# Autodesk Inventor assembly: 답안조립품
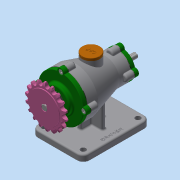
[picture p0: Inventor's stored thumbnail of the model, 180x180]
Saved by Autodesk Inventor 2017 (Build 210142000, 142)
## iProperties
Part Number: 답안조립품
Material: 일반
Document SubType Name: Assembly
Designer: 222
Author: 222
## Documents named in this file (15)
- C:\Users\222\Downloads\701206V1024\답안조립품.iam
- C:\Users\222\Downloads\701206V1024\본체.ipt
- C:\Users\222\Downloads\701206V1024\축.ipt
- C:\Users\222\Downloads\701206V1024\베어링 6203.ipt
- C:\Users\222\Downloads\701206V1024\키 4x4x14.ipt
- C:\Users\222\Downloads\701206V1024\개스킷 A.ipt
- C:\Users\222\Downloads\701206V1024\개스킷 B.ipt
- C:\Users\222\Downloads\701206V1024\앞커버.ipt
- C:\Users\222\Downloads\701206V1024\오일 실 17 30 8.ipt
- C:\Users\222\Downloads\701206V1024\뒤커버.ipt
- C:\Users\222\Downloads\701206V1024\베어링 6200.ipt
- C:\Users\222\Downloads\701206V1024\오일 실 10 20 7.ipt
- C:\Users\222\Downloads\701206V1024\스프로킷.ipt
- C:\Users\222\Downloads\701206V1024\마개.ipt
- C:\Users\222\Downloads\701206V1024\볼트 M5.ipt
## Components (2 placed, 2 different names)
1. 개스킷 A:1
2. 개스킷 B:1
